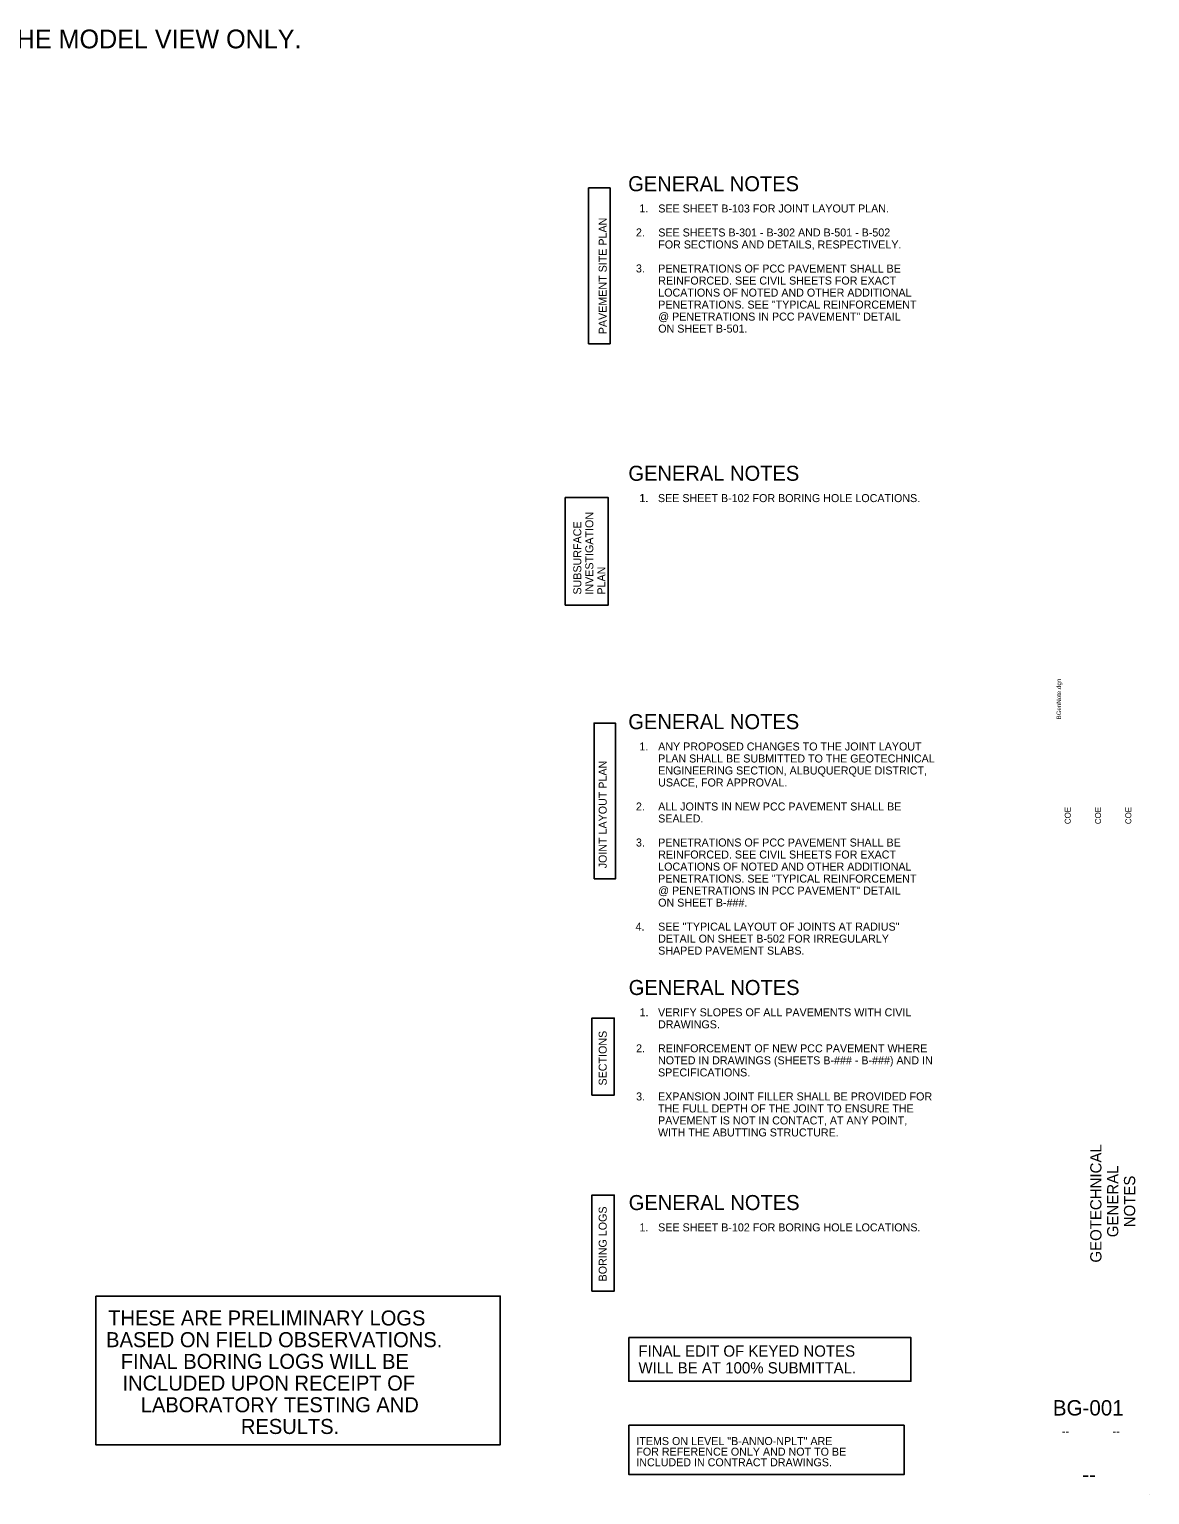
# Model space of a CAD drawing. Extents: x -0.19 to 2.72, y 0.17 to 2.08.
import ezdxf

# ---------------------------------------------------------------- set-up
doc = ezdxf.new("R2010")
doc.units = 0
for name, color, linetype in [('B-ANNO-NOTE', 7, 'Continuous'), ('B-ANNO-NPLT', 7, 'Continuous'), ('G-ANNO-TEXT', 7, 'Continuous')]:
    doc.layers.add(name, color=color, linetype=linetype)

msp = doc.modelspace()

# ---------------------------------------------------------------- linework, layer by layer
at = {"layer": 'B-ANNO-NPLT'}
for points in [[(1.9904, 1.6689), (2.0183, 1.6689), (2.0183, 1.8713), (1.9904, 1.8713)], [(1.9601, 1.3292), (2.016, 1.3292), (2.016, 1.4688), (1.9601, 1.4688)], [(1.9974, 0.9733), (2.0253, 0.9733), (2.0253, 1.1757), (1.9974, 1.1757)], [(1.9946, 0.6923), (2.0238, 0.6923), (2.0238, 0.7925), (1.9946, 0.7925)], [(1.9946, 0.4376), (2.0238, 0.4376), (2.0238, 0.5624), (1.9946, 0.5624)], [(2.0427, 0.2632), (2.4003, 0.2632), (2.4003, 0.1992), (2.0427, 0.1992)]]:
    msp.add_lwpolyline(points, close=True, dxfattribs=at)
at = {"layer": 'G-ANNO-TEXT'}
msp.add_line((2.7196, 0.173), (2.7196, 0.173), dxfattribs=at)
for points in [[(1.3498, 0.4312), (1.8755, 0.4312), (1.8755, 0.238), (1.3498, 0.238)], [(2.0426, 0.3771), (2.4093, 0.3771), (2.4093, 0.3205), (2.0426, 0.3205)]]:
    msp.add_lwpolyline(points, close=True, dxfattribs=at)

# ---------------------------------------------------------------- texts
at = {"layer": 'B-ANNO-NOTE'}
for s, height, p in [('GENERAL NOTES', 0.019531, (2.0418, 1.867)), ('GENERAL NOTES', 0.019531, (2.0418, 1.867)), ('GENERAL NOTES', 0.019531, (2.0418, 1.867)), ('GENERAL NOTES', 0.019531, (2.0418, 1.867)), ('1.', 0.0104, (2.0564, 1.8396)), ('SEE SHEET B-103 FOR JOINT LAYOUT PLAN. ', 0.0104, (2.0809, 1.8394)), ('2.', 0.0104, (2.0519, 1.8083)), ('SEE SHEETS B-301 - B-302 AND B-501 - B-502', 0.0104, (2.0809, 1.8082)), ('FOR SECTIONS AND DETAILS, RESPECTIVELY. ', 0.0104, (2.0809, 1.7926)), ('3.', 0.0104, (2.0519, 1.7615)), ('PENETRATIONS OF PCC PAVEMENT SHALL BE ', 0.0104, (2.0809, 1.7613)), ('REINFORCED. SEE CIVIL SHEETS FOR EXACT ', 0.0104, (2.0809, 1.7457)), ('LOCATIONS OF NOTED AND OTHER ADDITIONAL ', 0.0104, (2.0809, 1.7301)), ('PENETRATIONS. SEE "TYPICAL REINFORCEMENT ', 0.0104, (2.0809, 1.7145)), ('@ PENETRATIONS IN PCC PAVEMENT" DETAIL ', 0.0104, (2.0809, 1.6989)), ('ON SHEET B-501.', 0.0104, (2.0809, 1.6833)), ('GENERAL NOTES', 0.019531, (2.0421, 1.4907)), ('1.', 0.0104, (2.0561, 1.463)), ('1.', 0.0104, (2.0566, 1.463)), ('SEE SHEET B-102 FOR BORING HOLE LOCATIONS.', 0.0104, (2.0805, 1.463)), ('GENERAL NOTES', 0.019531, (2.042, 1.1679)), ('1.', 0.0104, (2.0564, 1.1402)), ('ANY PROPOSED CHANGES TO THE JOINT LAYOUT ', 0.0104, (2.0808, 1.1402)), ('PLAN SHALL BE SUBMITTED TO THE GEOTECHNICAL', 0.0104, (2.0808, 1.1246)), ('ENGINEERING SECTION, ALBUQUERQUE DISTRICT, ', 0.0104, (2.0808, 1.109)), ('USACE, FOR APPROVAL. ', 0.0104, (2.0808, 1.0934)), ('2.', 0.0104, (2.0519, 1.0622)), ('ALL JOINTS IN NEW PCC PAVEMENT SHALL BE ', 0.0104, (2.0808, 1.0622)), ('SEALED. ', 0.0104, (2.0808, 1.0466)), ('3.', 0.0104, (2.0519, 1.0154)), ('PENETRATIONS OF PCC PAVEMENT SHALL BE ', 0.0104, (2.0808, 1.0154)), ('REINFORCED. SEE CIVIL SHEETS FOR EXACT ', 0.0104, (2.0808, 0.9998)), ('LOCATIONS OF NOTED AND OTHER ADDITIONAL ', 0.0104, (2.0808, 0.9841)), ('PENETRATIONS. SEE "TYPICAL REINFORCEMENT ', 0.0104, (2.0808, 0.9685)), ('@ PENETRATIONS IN PCC PAVEMENT" DETAIL ', 0.0104, (2.0808, 0.9529)), ('ON SHEET B-###.', 0.0104, (2.0808, 0.9373)), ('4.', 0.0104, (2.0514, 0.9061)), ('SEE "TYPICAL LAYOUT OF JOINTS AT RADIUS" ', 0.0104, (2.0808, 0.9061)), ('DETAIL ON SHEET B-502 FOR IRREGULARLY ', 0.0104, (2.0808, 0.8905)), ('SHAPED PAVEMENT SLABS.', 0.0104, (2.0808, 0.8749)), ('GENERAL NOTES', 0.019531, (2.0425, 0.8224)), ('1.', 0.0104, (2.0566, 0.7947)), ('VERIFY SLOPES OF ALL PAVEMENTS WITH CIVIL ', 0.0104, (2.0806, 0.7947)), ('DRAWINGS. ', 0.0104, (2.0806, 0.7791)), ('2.', 0.0104, (2.0521, 0.7479)), ('REINFORCEMENT OF NEW PCC PAVEMENT WHERE ', 0.0104, (2.0806, 0.7479)), ('NOTED IN DRAWINGS (SHEETS B-### - B-###) AND IN ', 0.0104, (2.0806, 0.7323)), ('SPECIFICATIONS. ', 0.0104, (2.0806, 0.7166)), ('3.', 0.0104, (2.0521, 0.6854)), ('EXPANSION JOINT FILLER SHALL BE PROVIDED FOR ', 0.0104, (2.0806, 0.6854)), ('THE FULL DEPTH OF THE JOINT TO ENSURE THE ', 0.0104, (2.0806, 0.6698)), ('WITH THE ABUTTING STRUCTURE. ', 0.0104, (2.0806, 0.6386)), ('PAVEMENT IS NOT IN CONTACT, AT ANY POINT, ', 0.0104, (2.0806, 0.6542)), ('GENERAL NOTES', 0.019531, (2.0425, 0.5429)), ('1.', 0.0104, (2.0565, 0.5152)), ('SEE SHEET B-102 FOR BORING HOLE LOCATIONS.', 0.0104, (2.0808, 0.5152))]:
    msp.add_text(s, height=height, rotation=360, dxfattribs=at).set_placement(p)
at = {"layer": 'B-ANNO-NPLT'}
for s, height, p in [('THIS SHEET CAN BE ATTACHED AS A CELL LIBRARY TO DGN FILES.  EDIT THIS SHEET IN THE MODEL VIEW ONLY. ', 0.024414, (-0.1932, 2.0527)), ('ITEMS ON LEVEL "B-ANNO-NPLT" ARE ', 0.0104, (2.0524, 0.2375)), ('FOR REFERENCE ONLY AND NOT TO BE ', 0.0104, (2.0524, 0.2237)), ('INCLUDED IN CONTRACT DRAWINGS. ', 0.0104, (2.0524, 0.2099))]:
    msp.add_text(s, height=height, dxfattribs=at).set_placement(p)
for s, p in [('PAVEMENT SITE PLAN', (2.0139, 1.6812)), ('INVESTIGATION', (1.9965, 1.3428)), ('SUBSURFACE', (1.9809, 1.3428)), ('PLAN', (2.0121, 1.3428)), ('JOINT LAYOUT PLAN', (2.0139, 0.987)), ('SECTIONS', (2.0139, 0.7048)), ('BORING LOGS', (2.0139, 0.4502))]:
    msp.add_text(s, height=0.0104, rotation=90, dxfattribs=at).set_placement(p)
at = {"layer": 'G-ANNO-TEXT'}
for s, height, p in [('BGenNote.dgn', 0.005785, (2.6044, 1.1806)), ('COE', 0.00769, (2.6169, 1.0445)), ('COE', 0.00768, (2.6563, 1.0445)), ('COE', 0.00769, (2.6956, 1.0445)), ('GEOTECHNICAL', 0.014583, (2.6569, 0.4746)), ('GENERAL', 0.01458, (2.6788, 0.5076)), ('NOTES', 0.01458, (2.7007, 0.5205))]:
    msp.add_text(s, height=height, rotation=90, dxfattribs=at).set_placement(p)
for s, height, p in [('THESE ARE PRELIMINARY LOGS ', 0.019531, (1.3661, 0.3929)), ('BASED ON FIELD OBSERVATIONS.', 0.019531, (1.3634, 0.3647)), ('FINAL EDIT OF KEYED NOTES', 0.014583, (2.055, 0.3524)), ('FINAL BORING LOGS WILL BE ', 0.019531, (1.3824, 0.3365)), ('WILL BE AT 100% SUBMITTAL.', 0.014583, (2.0552, 0.3306)), ('INCLUDED UPON RECEIPT OF ', 0.019531, (1.3847, 0.3083)), ('LABORATORY TESTING AND', 0.019531, (1.4084, 0.2801)), ('BG-001', 0.01997, (2.5937, 0.2759)), ('RESULTS. ', 0.01953, (1.5385, 0.2519)), ('--', 0.01042, (2.6055, 0.2502)), ('--', 0.01042, (2.6714, 0.2502)), ('--', 0.01997, (2.6319, 0.1893))]:
    msp.add_text(s, height=height, dxfattribs=at).set_placement(p)

doc.saveas('drawing.dxf')
